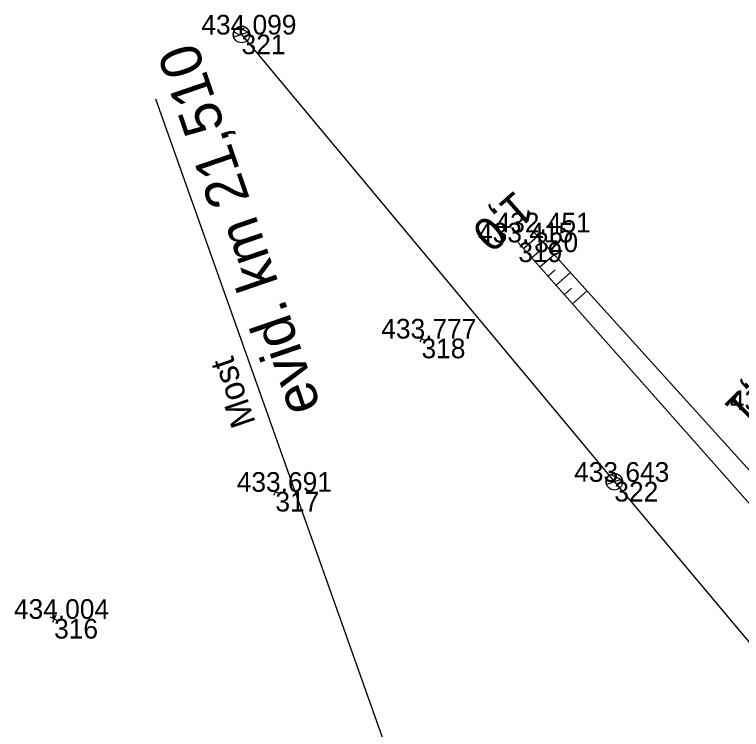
# Model space of a CAD drawing. Extents: x -751615 to -750797, y -1114905 to -1114561.
# Drawn here: x -751148.35 to -751104.04, y -1114663.24 to -1114619.67 of the extents above; entities that cross this region are included whole.
import ezdxf

# ---------------------------------------------------------------- set-up
doc = ezdxf.new("R2010")
doc.units = 0
for name, color, linetype in [('Vrstva 18', 7, 'Continuous'), ('Vrstva 25', 7, 'Continuous'), ('Vrstva 36', 7, 'Continuous'), ('Vrstva 48', 7, 'Continuous'), ('Vrstva 49', 7, 'Continuous'), ('Vrstva 50', 7, 'Continuous'), ('Vrstva 60', 7, 'Continuous'), ('Vrstva 61', 7, 'Continuous')]:
    doc.layers.add(name, color=color, linetype=linetype)

msp = doc.modelspace()

# ---------------------------------------------------------------- linework, layer by layer
at = {"layer": 'Vrstva 18'}
msp.add_line((-751120.982, -1114677.614), (-751139.734, -1114624.839), dxfattribs=at)
at = {"layer": 'Vrstva 25'}
msp.add_lwpolyline([(-751134.515, -1114620.892), (-751111.788, -1114648.149), (-751079.416, -1114686.713)], dxfattribs=at)
at = {"layer": 'Vrstva 36'}
for p, q in [((-751134.039, -1114620.728), (-751134.991, -1114621.056)), ((-751134.99, -1114620.736), (-751134.606, -1114620.923)), ((-751134.737, -1114620.442), (-751134.105, -1114620.75)), ((-751112.01, -1114647.699), (-751111.378, -1114648.007)), ((-751111.312, -1114647.985), (-751112.264, -1114648.313)), ((-751112.263, -1114647.993), (-751111.879, -1114648.18))]:
    msp.add_line(p, q, dxfattribs=at)
for centre in [(-751134.515, -1114620.892), (-751111.788, -1114648.149)]:
    msp.add_circle(centre, 0.503, dxfattribs=at)
for centre in [(-751134.515, -1114620.892), (-751111.788, -1114648.149)]:
    msp.add_arc(centre, 0.503, 19.0308, 199.0308, dxfattribs=at)
at = {"layer": 'Vrstva 48'}
for p, q in [((-751117.322, -1114633.927), (-751116.473, -1114633.176)), ((-751116.825, -1114634.489), (-751116.397, -1114634.11)), ((-751116.328, -1114635.05), (-751115.467, -1114634.288)), ((-751115.831, -1114635.612), (-751115.397, -1114635.228)), ((-751115.334, -1114636.173), (-751114.46, -1114635.401)), ((-751114.836, -1114636.735), (-751114.397, -1114636.346)), ((-751114.339, -1114637.297), (-751113.454, -1114636.513))]:
    msp.add_line(p, q, dxfattribs=at)
at = {"layer": 'Vrstva 49'}
for p, q in [((-751123.321, -1114639.529), (-751123.771, -1114639.311)), ((-751123.437, -1114639.195), (-751123.655, -1114639.645)), ((-751132.227, -1114648.868), (-751132.677, -1114648.648)), ((-751132.342, -1114648.533), (-751132.562, -1114648.983)), ((-751145.715, -1114656.611), (-751146.165, -1114656.391)), ((-751145.83, -1114656.276), (-751146.05, -1114656.726))]:
    msp.add_line(p, q, dxfattribs=at)
for points in [[(-751116.675, -1114632.953), (-751098.674, -1114652.847), (-751090.21, -1114660.329), (-751083.98, -1114663.255), (-751079.08, -1114670.424), (-751065.412, -1114686.286)], [(-751117.644, -1114633.563), (-751099.898, -1114653.612), (-751091.377, -1114661.254), (-751084.998, -1114664.191), (-751079.852, -1114671.705), (-751066.794, -1114687.156)]]:
    msp.add_lwpolyline(points, dxfattribs=at)
at = {"layer": 'Vrstva 50'}
msp.add_lwpolyline([(-751116.675, -1114632.953), (-751098.674, -1114652.847), (-751090.21, -1114660.329), (-751083.98, -1114663.255), (-751079.08, -1114670.424), (-751065.412, -1114686.286)], dxfattribs=at)
at = {"layer": 'Vrstva 60'}
for p, q in [((-751134.515, -1114620.892), (-751134.515, -1114620.892)), ((-751116.675, -1114632.953), (-751116.675, -1114632.953)), ((-751117.644, -1114633.563), (-751117.644, -1114633.563)), ((-751123.546, -1114639.42), (-751123.546, -1114639.42)), ((-751111.788, -1114648.149), (-751111.788, -1114648.149)), ((-751132.452, -1114648.758), (-751132.452, -1114648.758)), ((-751145.94, -1114656.501), (-751145.94, -1114656.501))]:
    msp.add_line(p, q, dxfattribs=at)

# ---------------------------------------------------------------- texts
at = {"layer": 'Vrstva 18'}
for s, height, p in [('evid. km 21,510', 2.5, (-751129.66, -1114643.575)), ('Most', 1.5, (-751133.647, -1114644.533))]:
    msp.add_text(s, height=height, rotation=108.91, dxfattribs=at).set_placement(p)
at = {"layer": 'Vrstva 48'}
for s, rotation, p in [('1,0', 221.5131, (-751117.82, -1114630.307)), ('1,1', 224.8302, (-751102.533, -1114640.88))]:
    msp.add_text(s, height=2, rotation=rotation, dxfattribs=at).set_placement(p)
at = {"layer": 'Vrstva 60'}
for s, p in [('321', (-751134.515, -1114622.092)), ('320', (-751116.675, -1114634.153)), ('319', (-751117.644, -1114634.763)), ('318', (-751123.546, -1114640.62)), ('322', (-751111.788, -1114649.349)), ('317', (-751132.452, -1114649.958)), ('316', (-751145.94, -1114657.701))]:
    msp.add_text(s, height=1.2, dxfattribs=at).set_placement(p)
at = {"layer": 'Vrstva 61'}
for s, p in [('434.099', (-751136.969, -1114620.892)), ('432.451', (-751119.032, -1114632.953)), ('433.415', (-751120.1, -1114633.563)), ('433.777', (-751125.998, -1114639.42)), ('432.569', (-751104.742, -1114643.771)), ('433.643', (-751114.24, -1114648.149)), ('433.691', (-751134.809, -1114648.758)), ('434.004', (-751148.391, -1114656.501))]:
    msp.add_text(s, height=1.2, dxfattribs=at).set_placement(p)

doc.saveas('drawing.dxf')
